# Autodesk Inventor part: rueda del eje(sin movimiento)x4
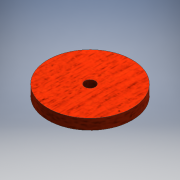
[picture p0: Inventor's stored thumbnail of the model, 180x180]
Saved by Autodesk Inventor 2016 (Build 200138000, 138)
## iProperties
Created: 2016-06
Part Number: rueda del eje(sin movimiento)x4
Material: Genérico
Document SubType Name: Modeling
Designer: adm
Density: 1 g/cm^3
Appearance: Valor por defecto
Author: adm
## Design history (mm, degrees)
sketch "Boceto1"
  geometry: C1 r 40 at (0, 0); 1 further point
  constraints: 1 centre point, 1 coincident
  dimensions: "d0" = 80 diameter of C1
extrude "Extrusión1" new body sketch "Boceto1" distance "d1" = 10; taper "d2" = 0 deg
sketch "Boceto2"
  geometry: C1 r 5 at (0, 0); 1 further point
  constraints: 1 centre point, 1 coincident
  dimensions: "d3" = 10 diameter of C1
extrude "Extrusión2" cut sketch "Boceto2" distance "d4" = 10; taper "d5" = 0 deg
node "Sólido1"
